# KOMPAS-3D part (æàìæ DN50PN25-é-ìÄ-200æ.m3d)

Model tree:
1. Объединить компоненты:1  (labels: СЕНС DN50PN25-В-НО-200С)

Referenced files in D:\Савин\!СЕНСОР\3D для заказчика\!Новый перечень\СЕНС\7. СЕНС-В-НО-200С\DN50\: СЕНС DN50PN25-В-НО-200С.a3d
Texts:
  СЕНС DN50PN25-В-НО-200С
  ООО НПП Сенсор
